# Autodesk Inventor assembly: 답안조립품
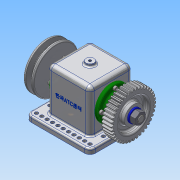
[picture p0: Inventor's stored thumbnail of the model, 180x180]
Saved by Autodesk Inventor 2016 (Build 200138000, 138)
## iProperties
Created: 2018-11
Part Number: 답안조립품
Material: 일반
Document SubType Name: Assembly
Designer: 605-15
Author: 605-15
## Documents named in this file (13)
- C:\Users\605-15\Desktop\481108V1021\답안조립품.iam
- C:\Users\605-15\Desktop\481108V1021\V벨트풀리.ipt
- C:\Users\605-15\Desktop\481108V1021\너트 M12x1.25.ipt
- C:\Users\605-15\Desktop\481108V1021\베어링 6203.ipt
- C:\Users\605-15\Desktop\481108V1021\본체.ipt
- C:\Users\605-15\Desktop\481108V1021\볼트 M4.ipt
- C:\Users\605-15\Desktop\481108V1021\부시.ipt
- C:\Users\605-15\Desktop\481108V1021\스퍼기어.ipt
- C:\Users\605-15\Desktop\481108V1021\오일 실 26 38 8.ipt
- C:\Users\605-15\Desktop\481108V1021\와셔 12x24.ipt
- C:\Users\605-15\Desktop\481108V1021\축.ipt
- C:\Users\605-15\Desktop\481108V1021\커버.ipt
- C:\Users\605-15\Desktop\481108V1021\키 5x5x12.ipt
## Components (1 placed, 1 different names)
1. V벨트풀리:1 — 각도:6
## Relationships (1: Angle 1)
- 각도:6 [Angle]: V벨트풀리:1
